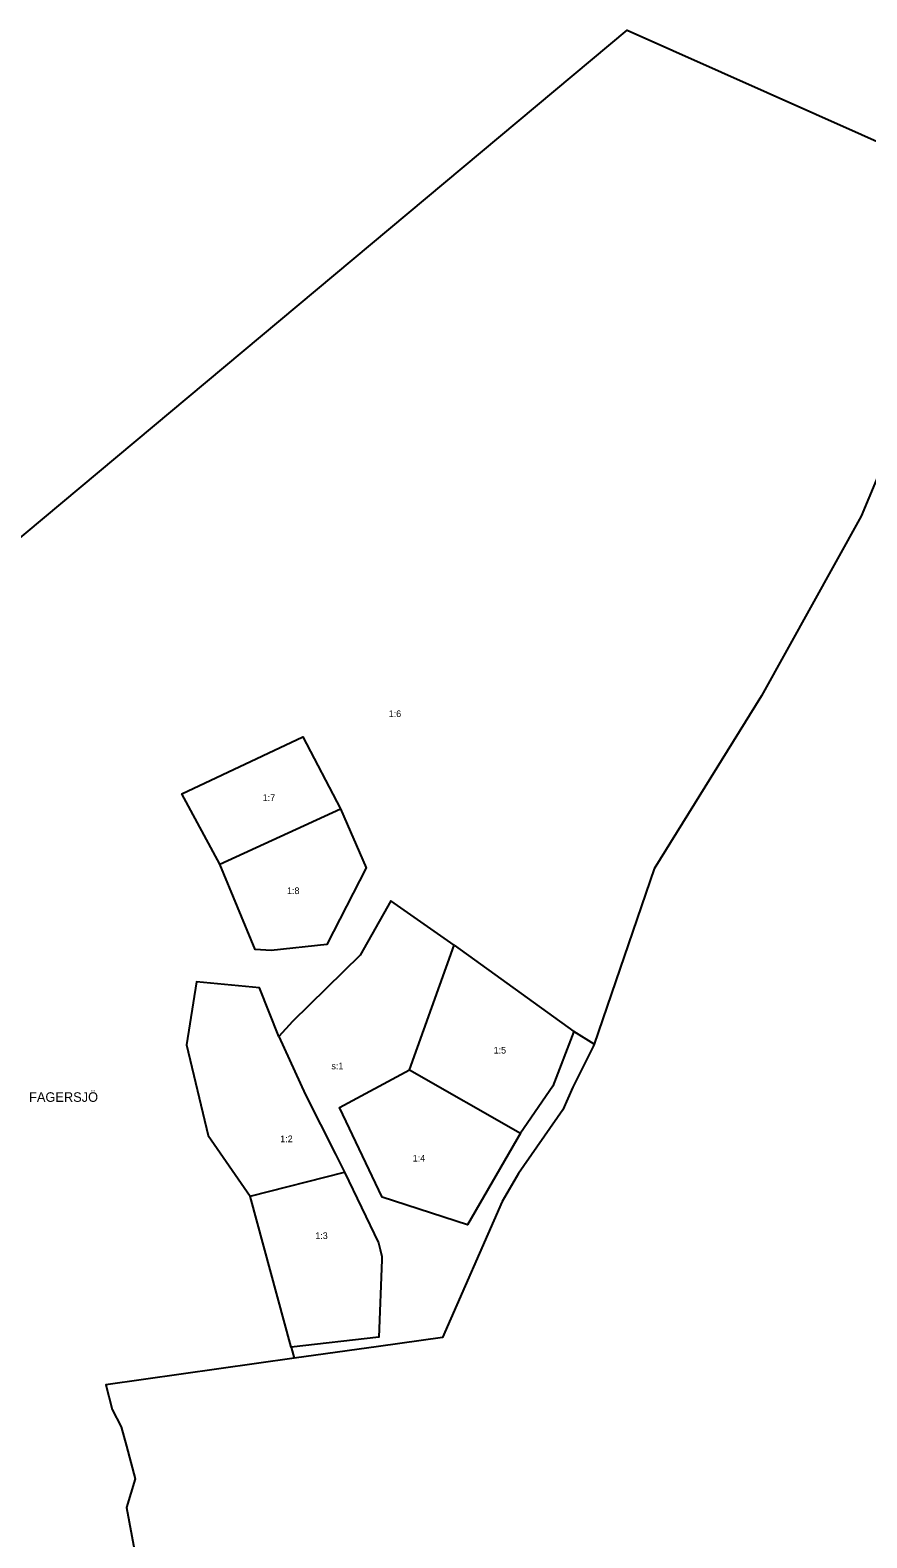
# Model space of a CAD drawing. Extents: x 140824 to 143748, y 6547319 to 6550906.
# Drawn here: x 141835 to 142272, y 6548751 to 6549539 of the extents above; entities that cross this region are included whole.
import ezdxf

# ---------------------------------------------------------------- set-up
doc = ezdxf.new("R2010")
doc.units = 0
for name, color, linetype in [('FAST Fastighetsgräns', 7, 'Continuous'), ('FAST Registernummer för fastighet', 7, 'Continuous'), ('FAST Registernummer för samfällighet', 7, 'Continuous'), ('FAST Traktgräns', 7, 'Continuous'), ('FAST Traktnamn', 7, 'Continuous')]:
    doc.layers.add(name, color=color, linetype=linetype)

msp = doc.modelspace()

# ---------------------------------------------------------------- linework, layer by layer
at = {"layer": 'FAST Fastighetsgräns'}
for p, q in [((141933.76, 6549103.19), (141996.82, 6549131.99)), ((142033.04, 6548995.63), (142056.36, 6549060.85)), ((142056.36, 6549060.85), (142118.81, 6549015.63)), ((142129.44, 6549008.95), (142118.81, 6549015.63)), ((142033.04, 6548995.63), (142090.91, 6548962.57)), ((141949.64, 6548929.53), (141998.95, 6548942.11)), ((141971.07, 6548850.65), (141949.64, 6548929.53)), ((141971.07, 6548850.65), (141972.63, 6548844.89))]:
    msp.add_line(p, q, dxfattribs=at)
for points in [[(141933.76, 6549103.19), (141914.04, 6549139.91), (141977.14, 6549169.71), (141996.82, 6549131.99)], [(141996.82, 6549131.99), (142010.27, 6549101.14), (141989.79, 6549061.21), (141960.65, 6549058.04), (141952.28, 6549058.59), (141933.76, 6549103.19)], [(142056.36, 6549060.85), (142023.15, 6549084.04), (142007.13, 6549055.58), (141971.88, 6549020.8), (141964.6, 6549013.05)], [(141964.6, 6549013.05), (141954.49, 6549038.42), (141921.57, 6549041.58), (141916.41, 6549008.74), (141927.75, 6548961.32), (141949.64, 6548929.53)], [(141964.6, 6549013.05), (141978.53, 6548982.54), (141994.2, 6548951.52), (141998.95, 6548942.11)], [(142118.81, 6549015.63), (142107.79, 6548987), (142090.91, 6548962.57)], [(142090.91, 6548962.57), (142063.2, 6548914.52), (142018.68, 6548929.1), (141996.31, 6548975.91), (142033.04, 6548995.63)], [(141998.95, 6548942.11), (142016.83, 6548905.15), (142017.7, 6548901.63), (142018.58, 6548898.08), (142018.51, 6548896.22), (142016.95, 6548855.92), (141971.07, 6548850.65)]]:
    msp.add_lwpolyline(points, dxfattribs=at)
at = {"layer": 'FAST Traktgräns'}
for points in [[(141669.62, 6549140.14), (142146.68, 6549539.12), (142318.55, 6549462.6)], [(142281.87, 6549315.97), (142269.02, 6549284.98), (142216.86, 6549191.14), (142160.87, 6549100.73), (142129.44, 6549008.95)], [(142129.44, 6549008.95), (142129.11, 6549008.21), (142118.4, 6548986.55), (142113.01, 6548974.72), (142089.92, 6548941.45), (142081.44, 6548926.72), (142050.12, 6548855.7), (142016.76, 6548851.05), (141972.63, 6548844.89)], [(141972.63, 6548844.89), (141874.33, 6548830.86), (141877.61, 6548818.09), (141882.35, 6548808.96), (141885.06, 6548798.88), (141889.56, 6548781.75), (141885.13, 6548766.87), (141892.91, 6548724.65), (141925.47, 6548674.71), (141912.47, 6548640.08)]]:
    msp.add_lwpolyline(points, dxfattribs=at)

# ---------------------------------------------------------------- texts
at = {"layer": 'FAST Registernummer för fastighet'}
for s, p in [('1:6', (142022.1, 6549180.02)), ('1:7', (141956.24, 6549136.14)), ('1:8', (141968.95, 6549087.48)), ('1:5', (142076.93, 6549004.12)), ('1:2', (141965.4, 6548957.77)), ('1:4', (142034.64, 6548947.66)), ('1:3', (141983.73, 6548907.15))]:
    msp.add_text(s, height=3.5, dxfattribs=at).set_placement(p)
at = {"layer": 'FAST Registernummer för samfällighet'}
msp.add_text('s:1', height=3.5, dxfattribs=at).set_placement((141992.16, 6548995.87))
at = {"layer": 'FAST Traktnamn'}
msp.add_text('FAGERSJÖ', height=5, dxfattribs=at).set_placement((141834.16, 6548978.88))

doc.saveas('drawing.dxf')
